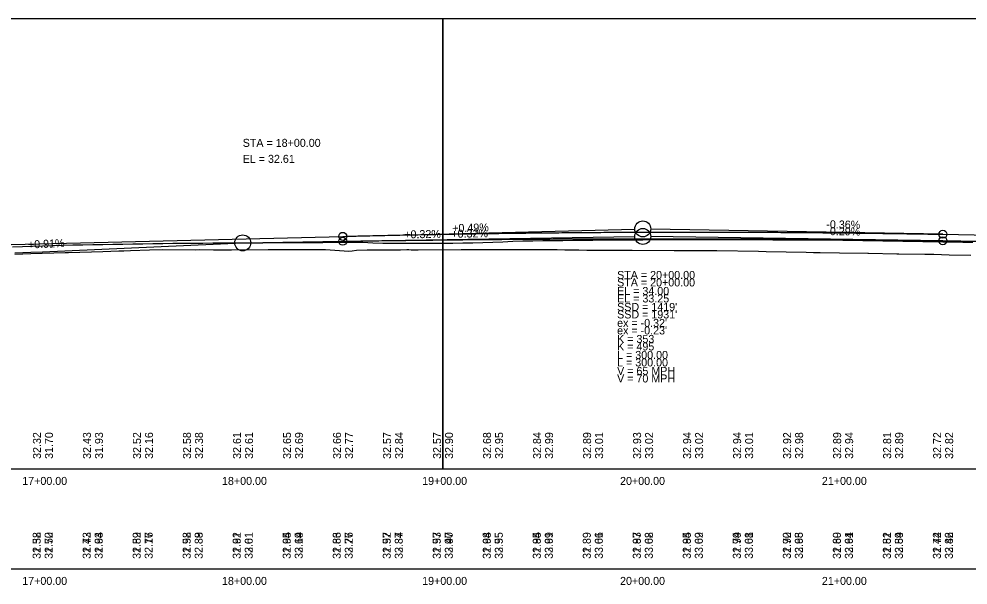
# Model space of a CAD drawing. Extents: x 3880794 to 3915434, y 287517 to 300173.
# Drawn here: x 3882226.5 to 3882700.9, y 297716.1 to 297999.2 of the extents above; entities that cross this region are included whole.
import ezdxf

# ---------------------------------------------------------------- set-up
doc = ezdxf.new("R2010")
doc.units = 0
for name, color, linetype in [('Level 1', 7, 'Continuous'), ('Level 2', 7, 'Continuous'), ('Level 30', 7, 'Continuous'), ('Level 31', 7, 'Continuous'), ('Level 32', 7, 'Continuous'), ('Level 62', 7, 'Continuous'), ('Level 63', 7, 'Continuous')]:
    doc.layers.add(name, color=color, linetype=linetype)

msp = doc.modelspace()

# ---------------------------------------------------------------- linework, layer by layer
at = {"layer": 'Level 1'}
for p, q in [((3882238.3, 297882.7), (3882338.3, 297887.24)), ((3882338.3, 297887.24), (3882388.3, 297888.04)), ((3882388.3, 297888.04), (3882534.3, 297890.38)), ((3882688.3, 297888.3), (3882542.3, 297890.38)), ((3882688.3, 297888.3), (3882884.3, 297885.5)), ((3882224.43, 297882.26), (3882232.31, 297882.54)), ((3882232.31, 297882.54), (3882238.3, 297882.7))]:
    msp.add_line(p, q, dxfattribs=at)
for points in [[(3882224.43, 297881.64), (3882232.31, 297881.91), (3882249.47, 297882.38), (3882251.25, 297882.46), (3882268.38, 297882.92)], [(3882268.38, 297882.92), (3882276.33, 297883.27), (3882278.82, 297883.33), (3882282.25, 297883.48), (3882291.72, 297883.74), (3882298.35, 297883.85), (3882314.73, 297883.8), (3882316.66, 297883.9), (3882323.67, 297883.79), (3882325.11, 297883.8), (3882332.73, 297883.77), (3882350.96, 297883.86), (3882352.92, 297883.85), (3882358.54, 297883.84), (3882378.01, 297883.97), (3882379.62, 297883.96), (3882391.39, 297883.13), (3882393.07, 297883.22), (3882395.2, 297883.64), (3882400.55, 297883.74), (3882417.14, 297883.79), (3882420.37, 297883.88), (3882421.3, 297883.88), (3882422.48, 297883.82), (3882426.05, 297883.82), (3882447.47, 297883.89), (3882449.38, 297883.89), (3882449.8, 297883.89), (3882471.41, 297883.86), (3882473.7, 297883.88), (3882474.38, 297883.95), (3882495.53, 297883.91), (3882499.36, 297883.79), (3882506.36, 297883.78), (3882510.24, 297883.66), (3882531.34, 297883.6), (3882532.9, 297883.54), (3882554.02, 297883.48), (3882557.91, 297883.47), (3882571.9, 297883.42), (3882575.32, 297883.41), (3882596.12, 297883), (3882600.02, 297882.95), (3882620.02, 297882.55), (3882623.65, 297882.43), (3882627.03, 297882.36), (3882636.61, 297882.21), (3882650.83, 297882.09), (3882651.17, 297882.08), (3882665.36, 297881.77), (3882665.74, 297881.76), (3882666.34, 297881.75), (3882679.27, 297881.63), (3882683.77, 297881.54), (3882691.39, 297881.28), (3882702.29, 297881.14)]]:
    msp.add_lwpolyline(points, dxfattribs=at)
for centre in [(3882538.3, 297890.44), (3882338.3, 297887.24)]:
    msp.add_circle(centre, 4, dxfattribs=at)
for points in [[(3882388.3, 297888.04), (3882394.3, 297888.14), (3882400.3, 297888.23), (3882406.3, 297888.31), (3882412.3, 297888.4), (3882418.3, 297888.48), (3882424.3, 297888.55), (3882430.3, 297888.62), (3882436.3, 297888.69), (3882442.3, 297888.76), (3882448.3, 297888.82), (3882454.3, 297888.88), (3882460.3, 297888.93), (3882466.3, 297888.98), (3882472.3, 297889.03), (3882478.3, 297889.07), (3882484.3, 297889.11), (3882490.3, 297889.15), (3882496.3, 297889.18), (3882502.3, 297889.21), (3882508.3, 297889.23), (3882514.3, 297889.26), (3882520.3, 297889.27), (3882526.3, 297889.29), (3882532.3, 297889.3), (3882538.3, 297889.3), (3882544.3, 297889.31), (3882550.3, 297889.31), (3882556.3, 297889.3), (3882562.3, 297889.3), (3882568.3, 297889.29), (3882574.3, 297889.27), (3882580.3, 297889.25), (3882586.3, 297889.23), (3882592.3, 297889.2), (3882598.3, 297889.17), (3882604.3, 297889.14), (3882610.3, 297889.1), (3882616.3, 297889.07), (3882622.3, 297889.02), (3882628.3, 297888.97), (3882634.3, 297888.92), (3882640.3, 297888.87), (3882646.3, 297888.81), (3882652.3, 297888.75), (3882658.3, 297888.68), (3882664.3, 297888.61), (3882670.3, 297888.54), (3882676.3, 297888.46), (3882682.3, 297888.38), (3882688.3, 297888.3)], [(3882688.3, 297888.3), (3882696.3, 297888.18), (3882704.3, 297888.06), (3882712.3, 297887.94), (3882720.3, 297887.81), (3882728.3, 297887.68), (3882736.3, 297887.54), (3882744.3, 297887.41), (3882752.3, 297887.26), (3882760.3, 297887.12), (3882768.3, 297886.97), (3882776.3, 297886.82), (3882784.3, 297886.66), (3882792.3, 297886.5), (3882800.3, 297886.33), (3882808.3, 297886.16), (3882816.3, 297885.99), (3882824.3, 297885.82), (3882832.3, 297885.64), (3882840.3, 297885.46), (3882848.3, 297885.27), (3882856.3, 297885.08), (3882864.3, 297884.88), (3882872.3, 297884.69), (3882880.3, 297884.48), (3882888.3, 297884.28), (3882896.3, 297884.07), (3882904.3, 297883.86), (3882912.3, 297883.64), (3882920.3, 297883.42), (3882928.3, 297883.2), (3882936.3, 297882.97), (3882944.3, 297882.74), (3882952.3, 297882.5), (3882960.3, 297882.27), (3882968.3, 297882.02), (3882976.3, 297881.78), (3882984.3, 297881.53), (3882992.3, 297881.27), (3883000.3, 297881.02), (3883008.3, 297880.76), (3883016.3, 297880.49), (3883024.3, 297880.22), (3883032.3, 297879.95), (3883040.3, 297879.67), (3883048.3, 297879.39), (3883056.3, 297879.11), (3883064.3, 297878.82), (3883072.3, 297878.53), (3883080.3, 297878.24), (3883088.3, 297877.94)]]:
    msp.add_spline(points, degree=3, dxfattribs=at)
at = {"layer": 'Level 2'}
for p, q in [((3882388.3, 297890.49), (3882534.3, 297894.09)), ((3882688.3, 297891.51), (3882542.3, 297894.12)), ((3882688.3, 297891.51), (3882738.3, 297890.62)), ((3881938.3, 297879.39), (3882388.3, 297890.49))]:
    msp.add_line(p, q, dxfattribs=at)
for points in [[(3882223.3, 297885.2), (3882228.3, 297885.39), (3882233.3, 297885.58), (3882238.3, 297885.77), (3882243.3, 297885.96), (3882248.3, 297886.09), (3882253.3, 297886.18), (3882258.3, 297886.27), (3882263.3, 297886.36), (3882268.3, 297886.45), (3882273.3, 297886.54), (3882278.3, 297886.63), (3882283.3, 297886.72), (3882288.3, 297886.81), (3882293.3, 297886.9), (3882298.3, 297886.99), (3882303.3, 297887.04), (3882308.3, 297887.07), (3882313.3, 297887.1), (3882318.3, 297887.14), (3882323.3, 297887.17), (3882328.3, 297887.2), (3882333.3, 297887.23), (3882338.3, 297887.26), (3882343.3, 297887.3), (3882348.3, 297887.33), (3882353.3, 297887.36), (3882358.3, 297887.39), (3882363.3, 297887.42), (3882368.3, 297887.45), (3882373.3, 297887.47), (3882378.3, 297887.48), (3882383.3, 297887.5), (3882388.3, 297887.51), (3882393.3, 297887.53), (3882398.3, 297887.54), (3882403.3, 297887.25), (3882408.3, 297887.02), (3882413.3, 297887.02), (3882418.3, 297887.03), (3882423.3, 297887.03), (3882428.3, 297887.04), (3882433.3, 297887.05), (3882438.3, 297887.06), (3882443.3, 297887.09), (3882448.3, 297887.19), (3882453.3, 297887.32), (3882458.3, 297887.44), (3882463.3, 297887.57), (3882468.3, 297887.69), (3882473.3, 297888.1), (3882478.3, 297888.27), (3882483.3, 297888.33), (3882488.3, 297888.38), (3882493.3, 297888.43), (3882498.3, 297888.48), (3882503.3, 297888.53), (3882508.3, 297888.59), (3882513.3, 297888.64), (3882518.3, 297888.69), (3882523.3, 297888.74), (3882528.3, 297888.79), (3882533.3, 297888.81), (3882538.3, 297888.82)], [(3882538.3, 297888.82), (3882543.3, 297888.84), (3882548.3, 297888.86), (3882553.3, 297888.87), (3882558.3, 297888.89), (3882563.3, 297888.91), (3882568.3, 297888.92), (3882573.3, 297888.94), (3882578.3, 297888.94), (3882583.3, 297888.92), (3882588.3, 297888.9), (3882593.3, 297888.87), (3882598.3, 297888.85), (3882603.3, 297888.83), (3882608.3, 297888.8), (3882613.3, 297888.78), (3882618.3, 297888.75), (3882623.3, 297888.73), (3882628.3, 297888.71), (3882633.3, 297888.69), (3882638.3, 297888.63), (3882643.3, 297888.55), (3882648.3, 297888.47), (3882653.3, 297888.39), (3882658.3, 297888.3), (3882663.3, 297888.22), (3882668.3, 297888.13), (3882673.3, 297888.05), (3882678.3, 297887.97), (3882683.3, 297887.89), (3882688.3, 297887.8), (3882693.3, 297887.72), (3882698.3, 297887.65), (3882703.3, 297887.58)]]:
    msp.add_lwpolyline(points, dxfattribs=at)
for centre, radius in [((3882538.3, 297894.19), 4), ((3882388.3, 297890.49), 2), ((3882688.3, 297891.51), 2)]:
    msp.add_circle(centre, radius, dxfattribs=at)
msp.add_spline([(3882388.3, 297890.49), (3882394.3, 297890.64), (3882400.3, 297890.78), (3882406.3, 297890.91), (3882412.3, 297891.04), (3882418.3, 297891.17), (3882424.3, 297891.29), (3882430.3, 297891.4), (3882436.3, 297891.51), (3882442.3, 297891.62), (3882448.3, 297891.72), (3882454.3, 297891.81), (3882460.3, 297891.9), (3882466.3, 297891.98), (3882472.3, 297892.06), (3882478.3, 297892.14), (3882484.3, 297892.21), (3882490.3, 297892.27), (3882496.3, 297892.33), (3882502.3, 297892.38), (3882508.3, 297892.43), (3882514.3, 297892.47), (3882520.3, 297892.51), (3882526.3, 297892.54), (3882532.3, 297892.57), (3882538.3, 297892.6), (3882544.3, 297892.61), (3882550.3, 297892.63), (3882556.3, 297892.63), (3882562.3, 297892.64), (3882568.3, 297892.63), (3882574.3, 297892.63), (3882580.3, 297892.61), (3882586.3, 297892.6), (3882592.3, 297892.57), (3882598.3, 297892.54), (3882604.3, 297892.51), (3882610.3, 297892.47), (3882616.3, 297892.43), (3882622.3, 297892.38), (3882628.3, 297892.33), (3882634.3, 297892.27), (3882640.3, 297892.21), (3882646.3, 297892.14), (3882652.3, 297892.06), (3882658.3, 297891.98), (3882664.3, 297891.9), (3882670.3, 297891.81), (3882676.3, 297891.72), (3882682.3, 297891.62), (3882688.3, 297891.51)], degree=3, dxfattribs=at)
at = {"layer": 'Level 31'}
for centre in [(3882388.3, 297888.04), (3882688.3, 297888.3), (3882688.3, 297888.3)]:
    msp.add_circle(centre, 2, dxfattribs=at)
at = {"layer": 'Level 62'}
for points in [[(3881738.3, 297774.19), (3882438.3, 297774.19), (3882438.3, 297999.19), (3881738.3, 297999.19)], [(3881738.3, 297774.19), (3882438.3, 297774.19), (3882438.3, 297999.19), (3881738.3, 297999.19)], [(3882438.3, 297774.19), (3883138.3, 297774.19), (3883138.3, 297999.19), (3882438.3, 297999.19)], [(3882438.3, 297774.19), (3883138.3, 297774.19), (3883138.3, 297999.19), (3882438.3, 297999.19)]]:
    msp.add_lwpolyline(points, close=True, dxfattribs=at)
at = {"layer": 'Level 63'}
msp.add_line((3881538.3, 297724.19), (3896411.35, 297724.19), dxfattribs=at)

# ---------------------------------------------------------------- texts
at = {"layer": 'Level 2'}
for s, rotation, p in [('+0.49%', 1.413, (3882443.07, 297892.58)), ('-0.36%', 358.977, (3882630, 297894.55))]:
    msp.add_text(s, height=4, rotation=rotation, dxfattribs=at).set_placement(p)
for s, p in [('STA = 20+00.00', (3882525.46, 297869.19)), ('EL = 34.00', (3882525.46, 297861.19)), ("SSD = 1419'", (3882525.46, 297853.19)), ("ex = -0.32'", (3882525.46, 297845.19)), ('K = 353', (3882525.46, 297837.19)), ('L = 300.00', (3882525.46, 297829.19)), ('V = 65 MPH', (3882525.46, 297821.19))]:
    msp.add_text(s, height=4, dxfattribs=at).set_placement(p)
at = {"layer": 'Level 30'}
for s, p in [('17+00.00', (3882228.09, 297766.19)), ('17+00.00', (3882228.09, 297766.19)), ('18+00.00', (3882327.94, 297766.19)), ('18+00.00', (3882327.94, 297766.19)), ('19+00.00', (3882428, 297766.19)), ('19+00.00', (3882428, 297766.19)), ('20+00.00', (3882526.93, 297766.19)), ('20+00.00', (3882526.93, 297766.19)), ('21+00.00', (3882627.81, 297766.19)), ('21+00.00', (3882627.81, 297766.19)), ('17+00.00', (3882228.09, 297716.19)), ('17+00.00', (3882228.09, 297716.19)), ('18+00.00', (3882327.94, 297716.19)), ('18+00.00', (3882327.94, 297716.19)), ('19+00.00', (3882428, 297716.19)), ('19+00.00', (3882428, 297716.19)), ('20+00.00', (3882526.93, 297716.19)), ('20+00.00', (3882526.93, 297716.19)), ('21+00.00', (3882627.81, 297716.19)), ('21+00.00', (3882627.81, 297716.19))]:
    msp.add_text(s, height=4, dxfattribs=at).set_placement(p)
at = {"layer": 'Level 31'}
for s, p in [('STA = 18+00.00', (3882338.3, 297935.24)), ('EL = 32.61', (3882338.3, 297927.24)), ('STA = 20+00.00', (3882525.46, 297865.44)), ('EL = 33.25', (3882525.46, 297857.44)), ("SSD = 1931'", (3882525.46, 297849.44)), ("ex = -0.23'", (3882525.46, 297841.44)), ('K = 495', (3882525.46, 297833.44)), ('L = 300.00', (3882525.46, 297825.44)), ('V = 70 MPH', (3882525.46, 297817.44))]:
    msp.add_text(s, height=4, dxfattribs=at).set_placement(p)
for s, rotation, p in [('+0.32%', 0.9167, (3882419.07, 297889.45)), ('+0.32%', 0.9167, (3882419.09, 297889.45)), ('+0.32%', 0.9167, (3882442.63, 297889.76)), ('+0.32%', 0.9167, (3882442.66, 297889.76)), ('-0.29%', 359.1815, (3882630.03, 297891.13)), ('+0.91%', 2.5993, (3882231.04, 297884.37)), ('31.70', 90, (3882243.44, 297779.19)), ('31.93', 90, (3882268.44, 297779.19)), ('32.16', 90, (3882293.44, 297779.19)), ('32.38', 90, (3882318.44, 297779.19)), ('32.61', 90, (3882343.44, 297779.19)), ('32.69', 90, (3882368.44, 297779.19)), ('32.77', 90, (3882393.44, 297779.19)), ('32.84', 90, (3882418.44, 297779.19)), ('32.90', 90, (3882443.44, 297779.19)), ('32.95', 90, (3882468.44, 297779.19)), ('32.99', 90, (3882493.44, 297779.19)), ('33.01', 90, (3882518.44, 297779.19)), ('33.02', 90, (3882543.44, 297779.19)), ('33.02', 90, (3882568.44, 297779.19)), ('33.01', 90, (3882593.44, 297779.19)), ('32.98', 90, (3882618.44, 297779.19)), ('32.94', 90, (3882643.44, 297779.19)), ('32.89', 90, (3882668.44, 297779.19)), ('32.82', 90, (3882693.44, 297779.19)), ('31.58', 90, (3882237.3, 297729.19)), ('31.70', 90, (3882243.3, 297729.19)), ('31.72', 90, (3882262.3, 297729.19)), ('31.93', 90, (3882268.3, 297729.19)), ('31.89', 90, (3882287.3, 297729.19)), ('32.16', 90, (3882293.3, 297729.19)), ('31.92', 90, (3882312.3, 297729.19)), ('32.38', 90, (3882318.3, 297729.19)), ('31.92', 90, (3882337.3, 297729.19)), ('32.61', 90, (3882343.3, 297729.19)), ('31.94', 90, (3882362.3, 297729.19)), ('32.69', 90, (3882368.3, 297729.19)), ('31.83', 90, (3882387.3, 297729.19)), ('32.77', 90, (3882393.3, 297729.19)), ('31.92', 90, (3882412.3, 297729.19)), ('32.84', 90, (3882418.3, 297729.19)), ('31.93', 90, (3882437.3, 297729.19)), ('32.90', 90, (3882443.3, 297729.19)), ('31.94', 90, (3882462.3, 297729.19)), ('32.95', 90, (3882468.3, 297729.19)), ('31.95', 90, (3882487.3, 297729.19)), ('32.99', 90, (3882493.3, 297729.19)), ('31.89', 90, (3882512.3, 297729.19)), ('33.01', 90, (3882518.3, 297729.19)), ('31.87', 90, (3882537.3, 297729.19)), ('33.02', 90, (3882543.3, 297729.19)), ('31.85', 90, (3882562.3, 297729.19)), ('33.02', 90, (3882568.3, 297729.19)), ('31.79', 90, (3882587.3, 297729.19)), ('33.01', 90, (3882593.3, 297729.19)), ('31.70', 90, (3882612.3, 297729.19)), ('32.98', 90, (3882618.3, 297729.19)), ('31.60', 90, (3882637.3, 297729.19)), ('32.94', 90, (3882643.3, 297729.19)), ('31.52', 90, (3882662.3, 297729.19)), ('32.89', 90, (3882668.3, 297729.19)), ('31.44', 90, (3882687.3, 297729.19)), ('32.82', 90, (3882693.3, 297729.19))]:
    msp.add_text(s, height=4, rotation=rotation, dxfattribs=at).set_placement(p)
at = {"layer": 'Level 32'}
for s, p in [('32.32', (3882237.44, 297779.19)), ('32.43', (3882262.44, 297779.19)), ('32.52', (3882287.44, 297779.19)), ('32.58', (3882312.44, 297779.19)), ('32.61', (3882337.44, 297779.19)), ('32.65', (3882362.44, 297779.19)), ('32.66', (3882387.44, 297779.19)), ('32.57', (3882412.44, 297779.19)), ('32.57', (3882437.44, 297779.19)), ('32.68', (3882462.44, 297779.19)), ('32.84', (3882487.44, 297779.19)), ('32.89', (3882512.44, 297779.19)), ('32.93', (3882537.44, 297779.19)), ('32.94', (3882562.44, 297779.19)), ('32.94', (3882587.44, 297779.19)), ('32.92', (3882612.44, 297779.19)), ('32.89', (3882637.44, 297779.19)), ('32.81', (3882662.44, 297779.19)), ('32.72', (3882687.44, 297779.19)), ('32.32', (3882237.3, 297729.19)), ('32.52', (3882243.3, 297729.19)), ('32.43', (3882262.3, 297729.19)), ('32.64', (3882268.3, 297729.19)), ('32.52', (3882287.3, 297729.19)), ('32.77', (3882293.3, 297729.19)), ('32.58', (3882312.3, 297729.19)), ('32.89', (3882318.3, 297729.19)), ('32.61', (3882337.3, 297729.19)), ('33.01', (3882343.3, 297729.19)), ('32.65', (3882362.3, 297729.19)), ('33.14', (3882368.3, 297729.19)), ('32.66', (3882387.3, 297729.19)), ('33.26', (3882393.3, 297729.19)), ('32.57', (3882412.3, 297729.19)), ('33.37', (3882418.3, 297729.19)), ('32.57', (3882437.3, 297729.19)), ('33.47', (3882443.3, 297729.19)), ('32.68', (3882462.3, 297729.19)), ('33.55', (3882468.3, 297729.19)), ('32.84', (3882487.3, 297729.19)), ('33.61', (3882493.3, 297729.19)), ('32.89', (3882512.3, 297729.19)), ('33.66', (3882518.3, 297729.19)), ('32.93', (3882537.3, 297729.19)), ('33.68', (3882543.3, 297729.19)), ('32.94', (3882562.3, 297729.19)), ('33.69', (3882568.3, 297729.19)), ('32.94', (3882587.3, 297729.19)), ('33.68', (3882593.3, 297729.19)), ('32.92', (3882612.3, 297729.19)), ('33.65', (3882618.3, 297729.19)), ('32.89', (3882637.3, 297729.19)), ('33.61', (3882643.3, 297729.19)), ('32.81', (3882662.3, 297729.19)), ('33.54', (3882668.3, 297729.19)), ('32.72', (3882687.3, 297729.19)), ('33.46', (3882693.3, 297729.19))]:
    msp.add_text(s, height=4, rotation=90, dxfattribs=at).set_placement(p)

doc.saveas('drawing.dxf')
